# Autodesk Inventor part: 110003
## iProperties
Shininess: 64.0
Length Units: 11272
Angle Units: 11279
Time Units: 11290
Mass Units: 11286
Length Display Precision: 3
Angle Display Precision: 2
Compacted: True
Part Number: 110003
Document SubType Name: Modeling
Created: 2004-06
Designer: jpittman
Manufacturer: Standard
Standards Organization: Custom
Density: 0.0
Volumn: 0.0
Area: 0.0
PropertySet Name: Model Information
Control State: 0
Master: False
Checked Out: False
Translation Standard: STEP AP203
File Name: 110003
Preprocessor: PRO/ENGINEER BY PARAMETRIC TECHNOLOGY CORPORATION, 2001150
Postprocessor: Build: 081d, Release: 8 SP1 - Date: Tue 01/26/2004
Sent Units: INCHES
Uncertainty: 0.00019022974225369998
Author: jpittman
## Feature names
1. Base1
